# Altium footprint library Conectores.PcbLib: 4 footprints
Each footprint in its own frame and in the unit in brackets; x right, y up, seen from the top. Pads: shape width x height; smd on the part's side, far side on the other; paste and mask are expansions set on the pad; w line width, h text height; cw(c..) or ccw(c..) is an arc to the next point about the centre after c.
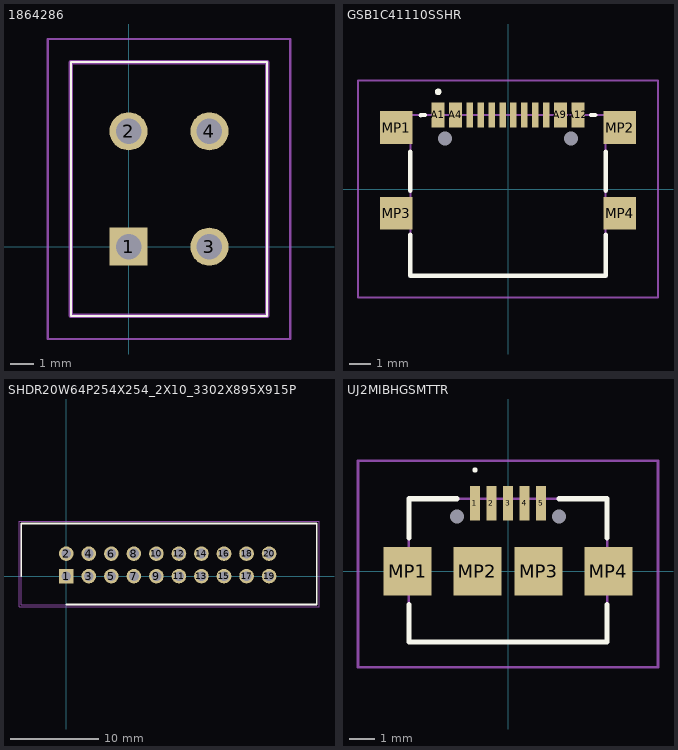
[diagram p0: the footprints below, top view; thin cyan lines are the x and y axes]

## 1864286 [mm]
pads (4):
  rect 1.65x1.65 hole 1.1: 1(0,0)
  round 1.65 hole 1.1: 2(0,5) 3(3.5,0) 4(3.5,5)
Top Overlay:
  lines w0.1: -2.5,-3 6,-3 6,8 -2.5,8 -2.5,-3
Mechanical 13:
  lines w0.2: -2.5,-3 6,-3 6,8 -2.5,8 -2.5,-3
Mechanical 15:
  lines w0.1: -3.5,-4 7,-4 7,9 -3.5,9 -3.5,-4
3D body "1864286.stp": height 11.42, standoff -2.08, extent -2.5,-3 6,8

## GSB1C41110SSHR [mm]
pads (18):
  rect 0.6x1.15 smd: A1(-3.2,3.39) A4(-2.4,3.39) A9(2.4,3.39) A12(3.2,3.39)
  rect 0.3x1.15 smd: A5(-1.25,3.39) A6(-0.25,3.39) A7(0.25,3.39) A8(1.25,3.39) B5(1.75,3.39) B6(0.75,3.39) B7(-0.75,3.39) B8(-1.75,3.39)
  round 0.325 hole 0.65 unplated: MH1(-2.89,2.315) MH2(2.89,2.315)
  rect 1.5x1.5 smd: MP1(-5.12,2.815) MP2(5.12,2.815) MP3(-5.12,-1.115) MP4(5.12,-1.115)
Top Overlay:
  lines w0.2: -4.47,-2.088 -4.47,-3.965 4.47,-3.965 4.47,-2.088 ; -4.47,-0.088 -4.47,1.712 ; -4,3.385 -3.8,3.39 ; 3.8,3.39 4,3.39 ; 4.47,-0.088 4.47,1.712 ; -3.2,4.4 cw(c-3.2,4.45) -3.2,4.5 ; -3.2,4.4 ccw(c-3.2,4.45) -3.2,4.5 ; -3.2,4.4 cw(c-3.2,4.45) -3.2,4.5
Mechanical 13:
  lines w0.1: -4.47,-3.965 -4.47,3.385 4.47,3.385 4.47,-3.965 -4.47,-3.965
Mechanical 15:
  lines w0.1: -6.87,-4.965 -6.87,4.965 6.87,4.965 6.87,-4.965 -6.87,-4.965
3D body "GSB1C41110SSHR.stp": height 3.12, standoff -0.76, extent -5.67,-4.088 5.67,3.51

## SHDR20W64P254X254_2X10_3302X895X915P [mm]
pads (20):
  rect 1.65x1.65 hole 1.1: 1(0,0)
  round 1.65 hole 1.1: 2(0,2.54) 3(2.54,0) 4(2.54,2.54) 5(5.08,0) 6(5.08,2.54) 7(7.62,0) 8(7.62,2.54) 9(10.16,0) 10(10.16,2.54) 11(12.7,0) 12(12.7,2.54) 13(15.24,0) 14(15.24,2.54) 15(17.78,0) 16(17.78,2.54) 17(20.32,0) 18(20.32,2.54) 19(22.86,0) 20(22.86,2.54)
Top Overlay:
  lines w0.2: -5.08,0 -5.08,5.945 28.24,5.945 28.24,-3.205 0,-3.205
Mechanical 13:
  lines w0.1: -5.08,-3.205 28.24,-3.205 28.24,5.945 -5.08,5.945 -5.08,-3.205
Mechanical 15:
  lines w0.05: -5.33,-3.455 28.49,-3.455 28.49,6.195 -5.33,6.195 -5.33,-3.455
3D body "T821120A1S100CEU.stp": height 9.15, standoff -3.55, extent -5.08,-3.205 27.94,5.745

## UJ2MIBHGSMTTR [mm]
pads (11):
  rect 0.4x1.35 smd: 1(-1.3,2.675) 2(-0.65,2.675) 3(0,2.675) 4(0.65,2.675) 5(1.3,2.675)
  round 0.275 hole 0.55 unplated: MH1(-2,2.15) MH2(2,2.15)
  rect 1.9x1.9 smd: MP1(-3.95,0) MP2(-1.2,0) MP3(1.2,0) MP4(3.95,0)
Top Overlay:
  lines w0.1: -1.3,3.935 cw(c-1.3,3.985) -1.3,4.035 cw(c-1.3,3.985) -1.3,3.935
  lines w0.2: -3.9,-1.3 -3.9,-2.78 3.9,-2.78 3.9,-1.3 ; -3.9,1.3 -3.9,2.85 -2,2.85 ; 2,2.85 3.9,2.85 3.9,1.3
Mechanical 13:
  lines w0.1: -3.9,-2.78 -3.9,2.85 3.9,2.85 3.9,-2.78 -3.9,-2.78
Mechanical 15:
  lines w0.1: -5.9,-3.78 -5.9,4.35 5.9,4.35 5.9,-3.78 -5.9,-3.78
3D body "UJ2-MIBH-G-SMT-TR.stp": height 2.58, standoff -0.67, extent -4.049,-2.828 4.051,2.815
